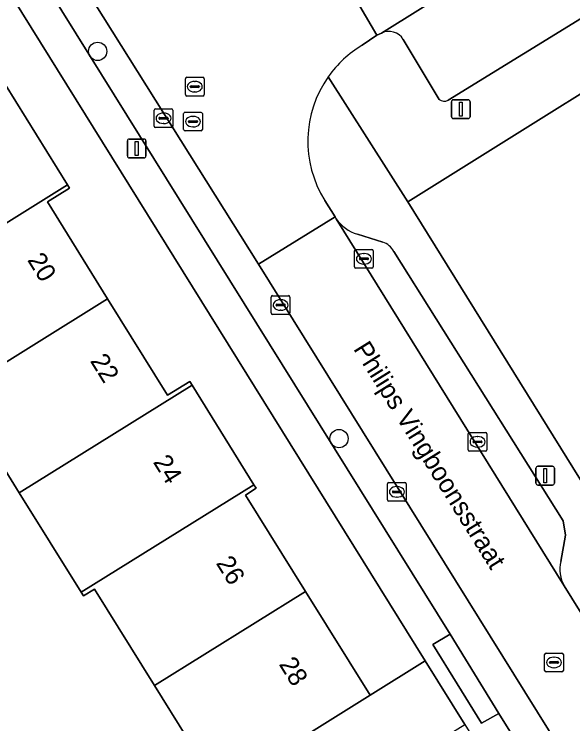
# Model space of a CAD drawing. Extents: x 159352 to 160617, y 385888 to 387323.
# Drawn here: x 159749.73 to 159779.61, y 385991.03 to 386028.96 of the extents above; entities that cross this region are included whole.
import ezdxf

# ---------------------------------------------------------------- set-up
doc = ezdxf.new("R2010")
doc.units = 0
for name, color, linetype in [('IMGEO_Boom', 7, 'Continuous'), ('IMGEO_Erf', 7, 'Continuous'), ('IMGEO_Kolk', 7, 'Continuous'), ('IMGEO_Lichtmast', 7, 'Continuous'), ('IMGEO_Openbare_ruimte_label', 7, 'Continuous'), ('IMGEO_Pand', 7, 'Continuous'), ('IMGEO_Pand_nummerreeks', 7, 'Continuous'), ('IMGEO_Parkeervlak_open', 7, 'Continuous'), ('IMGEO_Rijbaan_lokaal_open', 7, 'Continuous'), ('IMGEO_Rioolput', 7, 'Continuous'), ('IMGEO_Voetpad_open', 7, 'Continuous')]:
    doc.layers.add(name, color=color, linetype=linetype)

msp = doc.modelspace()

# ---------------------------------------------------------------- linework, layer by layer
at = {"layer": 'IMGEO_Boom'}
for centre in [(159754.195, 386026.974), (159767.101, 386006.278)]:
    msp.add_circle(centre, 0.489, dxfattribs=at)
at = {"layer": 'IMGEO_Erf'}
for points in [[(159749.263, 386025.183), (159752.591, 386019.833), (159752.697, 386019.663), (159751.507, 386018.93), (159754.731, 386013.749), (159757.937, 386008.596), (159759.127, 386009.334), (159759.247, 386009.14), (159762.552, 386003.808), (159762.666, 386003.623), (159762.111, 386003.252), (159765.311, 385998.105), (159768.762, 385992.557), (159771.719, 385994.399), (159746.307, 386035.207)], [(159743.864, 385985.314), (159750.4, 385989.412), (159752.465, 385986.118), (159755.303, 385987.897), (159756.968, 385985.218), (159760.702, 385987.531), (159757.239, 385993.08), (159754.026, 385998.227), (159753.441, 385997.869), (159753.321, 385998.062), (159750.006, 386003.387), (159746.677, 386008.735)]]:
    msp.add_lwpolyline(points, dxfattribs=at)
at = {"layer": 'IMGEO_Kolk'}
for p, q in [((159757.218, 386022.972), (159757.218, 386023.824)), ((159757.293, 386023.898), (159758.145, 386023.898)), ((159758.219, 386023.824), (159758.219, 386022.972)), ((159757.52, 386023.441), (159757.918, 386023.441)), ((159757.706, 386023.678), (159757.731, 386023.678)), ((159757.477, 386023.392), (159757.477, 386023.404)), ((159757.915, 386023.355), (159757.517, 386023.355)), ((159757.729, 386023.118), (159757.704, 386023.118)), ((159757.961, 386023.404), (159757.961, 386023.392)), ((159758.145, 386022.898), (159757.293, 386022.898)), ((159767.933, 386015.462), (159767.933, 386016.314)), ((159768.008, 386016.388), (159768.86, 386016.388)), ((159768.934, 386016.314), (159768.934, 386015.462)), ((159768.192, 386015.882), (159768.192, 386015.894)), ((159768.235, 386015.931), (159768.633, 386015.931)), ((159768.421, 386016.168), (159768.446, 386016.168)), ((159768.676, 386015.894), (159768.676, 386015.882)), ((159768.63, 386015.845), (159768.232, 386015.845)), ((159768.444, 386015.608), (159768.419, 386015.608)), ((159768.86, 386015.388), (159768.008, 386015.388)), ((159763.478, 386012.991), (159763.478, 386013.843)), ((159763.553, 386013.917), (159764.405, 386013.917)), ((159763.966, 386013.697), (159763.991, 386013.697)), ((159764.479, 386013.843), (159764.479, 386012.991)), ((159763.737, 386013.411), (159763.737, 386013.423)), ((159764.175, 386013.374), (159763.777, 386013.374)), ((159763.78, 386013.46), (159764.178, 386013.46)), ((159764.221, 386013.423), (159764.221, 386013.411)), ((159764.405, 386012.917), (159763.553, 386012.917)), ((159763.989, 386013.137), (159763.964, 386013.137)), ((159774.009, 386005.68), (159774.009, 386006.532)), ((159774.084, 386006.606), (159774.936, 386006.606)), ((159774.497, 386006.386), (159774.522, 386006.386)), ((159775.01, 386006.532), (159775.01, 386005.68)), ((159774.268, 386006.1), (159774.268, 386006.112)), ((159774.706, 386006.063), (159774.308, 386006.063)), ((159774.311, 386006.149), (159774.709, 386006.149)), ((159774.752, 386006.112), (159774.752, 386006.1)), ((159774.52, 386005.826), (159774.495, 386005.826)), ((159774.936, 386005.606), (159774.084, 386005.606)), ((159769.697, 386003.004), (159769.697, 386003.856)), ((159769.772, 386003.93), (159770.624, 386003.93)), ((159770.698, 386003.856), (159770.698, 386003.004)), ((159769.956, 386003.424), (159769.956, 386003.436)), ((159770.394, 386003.387), (159769.996, 386003.387)), ((159769.999, 386003.473), (159770.397, 386003.473)), ((159770.185, 386003.71), (159770.21, 386003.71)), ((159770.44, 386003.436), (159770.44, 386003.424)), ((159770.208, 386003.15), (159770.183, 386003.15)), ((159770.624, 386002.93), (159769.772, 386002.93))]:
    msp.add_line(p, q, dxfattribs=at)
for points in [[(159757.218, 386022.972), (159757.218, 386023.824)], [(159757.293, 386023.898), (159758.145, 386023.898)], [(159758.219, 386023.824), (159758.219, 386022.972)], [(159758.145, 386022.898), (159757.293, 386022.898)], [(159767.933, 386015.462), (159767.933, 386016.314)], [(159768.008, 386016.388), (159768.86, 386016.388)], [(159768.934, 386016.314), (159768.934, 386015.462)], [(159768.86, 386015.388), (159768.008, 386015.388)], [(159763.478, 386012.991), (159763.478, 386013.843)], [(159763.553, 386013.917), (159764.405, 386013.917)], [(159764.479, 386013.843), (159764.479, 386012.991)], [(159764.405, 386012.917), (159763.553, 386012.917)], [(159774.009, 386005.68), (159774.009, 386006.532)], [(159774.084, 386006.606), (159774.936, 386006.606)], [(159775.01, 386006.532), (159775.01, 386005.68)], [(159774.936, 386005.606), (159774.084, 386005.606)], [(159769.697, 386003.004), (159769.697, 386003.856)], [(159769.772, 386003.93), (159770.624, 386003.93)], [(159770.698, 386003.856), (159770.698, 386003.004)], [(159770.624, 386002.93), (159769.772, 386002.93)]]:
    msp.add_lwpolyline(points, dxfattribs=at)
for centre, radius, start, end in [((159757.295, 386023.822), 0.0765, 91.552, 178.448), ((159757.295, 386023.822), 0.0765, 91.552, 178.448), ((159758.143, 386023.822), 0.0765, 1.552, 88.448), ((159758.143, 386023.822), 0.0765, 1.552, 88.448), ((159757.517, 386023.401), 0.0403, 85.8775, 175.7526), ((159757.922, 386023.403), 0.0386, 1.7309, 96.639), ((159757.514, 386023.391), 0.0366, 178.938, 274.7102), ((159757.918, 386023.398), 0.043, 264.8664, 352.4533), ((159757.295, 386022.974), 0.0765, 181.552, 268.448), ((159757.295, 386022.974), 0.0765, 181.552, 268.448), ((159758.143, 386022.974), 0.0765, 271.552, 358.448), ((159758.143, 386022.974), 0.0765, 271.552, 358.448), ((159768.01, 386016.312), 0.0765, 91.552, 178.448), ((159768.01, 386016.312), 0.0765, 91.552, 178.448), ((159768.858, 386016.312), 0.0765, 1.552, 88.448), ((159768.858, 386016.312), 0.0765, 1.552, 88.448), ((159768.232, 386015.891), 0.0403, 85.8775, 175.7526), ((159768.229, 386015.881), 0.0366, 178.938, 274.7102), ((159768.633, 386015.888), 0.043, 264.8664, 352.4533), ((159768.637, 386015.893), 0.0386, 1.7309, 96.639), ((159768.01, 386015.464), 0.0765, 181.552, 268.448), ((159768.01, 386015.464), 0.0765, 181.552, 268.448), ((159768.858, 386015.464), 0.0765, 271.552, 358.448), ((159768.858, 386015.464), 0.0765, 271.552, 358.448), ((159763.555, 386013.841), 0.0765, 91.552, 178.448), ((159763.555, 386013.841), 0.0765, 91.552, 178.448), ((159764.403, 386013.841), 0.0765, 1.552, 88.448), ((159764.403, 386013.841), 0.0765, 1.552, 88.448), ((159763.777, 386013.42), 0.0403, 85.8775, 175.7526), ((159763.774, 386013.41), 0.0366, 178.938, 274.7102), ((159764.178, 386013.417), 0.043, 264.8664, 352.4533), ((159764.182, 386013.422), 0.0386, 1.7309, 96.639), ((159763.555, 386012.993), 0.0765, 181.552, 268.448), ((159763.555, 386012.993), 0.0765, 181.552, 268.448), ((159764.403, 386012.993), 0.0765, 271.552, 358.448), ((159764.403, 386012.993), 0.0765, 271.552, 358.448), ((159774.086, 386006.53), 0.0765, 91.552, 178.448), ((159774.086, 386006.53), 0.0765, 91.552, 178.448), ((159774.934, 386006.53), 0.0765, 1.552, 88.448), ((159774.934, 386006.53), 0.0765, 1.552, 88.448), ((159774.308, 386006.109), 0.0403, 85.8775, 175.7526), ((159774.305, 386006.099), 0.0366, 178.938, 274.7102), ((159774.709, 386006.106), 0.043, 264.8664, 352.4533), ((159774.713, 386006.111), 0.0386, 1.7309, 96.639), ((159774.086, 386005.682), 0.0765, 181.552, 268.448), ((159774.086, 386005.682), 0.0765, 181.552, 268.448), ((159774.934, 386005.682), 0.0765, 271.552, 358.448), ((159774.934, 386005.682), 0.0765, 271.552, 358.448), ((159769.774, 386003.854), 0.0765, 91.552, 178.448), ((159769.774, 386003.854), 0.0765, 91.552, 178.448), ((159770.622, 386003.854), 0.0765, 1.552, 88.448), ((159770.622, 386003.854), 0.0765, 1.552, 88.448), ((159769.996, 386003.433), 0.0403, 85.8775, 175.7526), ((159769.993, 386003.423), 0.0366, 178.938, 274.7102), ((159770.397, 386003.43), 0.043, 264.8664, 352.4533), ((159770.401, 386003.435), 0.0386, 1.7309, 96.639), ((159769.774, 386003.006), 0.0765, 181.552, 268.448), ((159769.774, 386003.006), 0.0765, 181.552, 268.448), ((159770.622, 386003.006), 0.0765, 271.552, 358.448), ((159770.622, 386003.006), 0.0765, 271.552, 358.448)]:
    msp.add_arc(centre, radius, start, end, dxfattribs=at)
for centre, major_axis, ratio, start_param, end_param in [((159757.705, 386023.398), (-0.387, 0.002), 0.722429, 4.712389, 7.853982), ((159757.73, 386023.398), (-0.39, 0.002), 0.717154, 1.570796, 4.712389), ((159768.42, 386015.888), (-0.387, 0.002), 0.722429, 4.712389, 7.853982), ((159768.445, 386015.888), (-0.39, 0.002), 0.717154, 1.570796, 4.712389), ((159763.965, 386013.417), (-0.387, 0.002), 0.722429, 4.712389, 7.853982), ((159763.99, 386013.417), (-0.39, 0.002), 0.717154, 1.570796, 4.712389), ((159774.496, 386006.106), (-0.387, 0.002), 0.722429, 4.712389, 7.853982), ((159774.521, 386006.106), (-0.39, 0.002), 0.717154, 1.570796, 4.712389), ((159770.184, 386003.43), (-0.387, 0.002), 0.722429, 4.712389, 7.853982), ((159770.209, 386003.43), (-0.39, 0.002), 0.717154, 1.570796, 4.712389)]:
    msp.add_ellipse(centre, major_axis=major_axis, ratio=ratio, start_param=start_param, end_param=end_param, dxfattribs=at)
at = {"layer": 'IMGEO_Lichtmast'}
for p, q in [((159773.12, 386023.484), (159773.12, 386024.284)), ((159773.12, 386024.284), (159773.12, 386023.484)), ((159773.22, 386024.384), (159774.01, 386024.384)), ((159774.01, 386024.384), (159773.22, 386024.384)), ((159774.11, 386024.284), (159774.11, 386023.484)), ((159774.11, 386023.484), (159774.11, 386024.284)), ((159774.01, 386023.384), (159773.22, 386023.384)), ((159773.22, 386023.384), (159774.01, 386023.384)), ((159755.787, 386021.385), (159755.787, 386022.185)), ((159755.787, 386022.185), (159755.787, 386021.385)), ((159755.887, 386022.285), (159756.677, 386022.285)), ((159756.677, 386022.285), (159755.887, 386022.285)), ((159756.777, 386022.185), (159756.777, 386021.385)), ((159756.777, 386021.385), (159756.777, 386022.185)), ((159756.677, 386021.285), (159755.887, 386021.285)), ((159755.887, 386021.285), (159756.677, 386021.285)), ((159777.631, 386003.896), (159777.631, 386004.696)), ((159777.631, 386004.696), (159777.631, 386003.896)), ((159777.731, 386004.796), (159778.521, 386004.796)), ((159778.521, 386004.796), (159777.731, 386004.796)), ((159778.621, 386004.696), (159778.621, 386003.896)), ((159778.621, 386003.896), (159778.621, 386004.696)), ((159778.521, 386003.796), (159777.731, 386003.796)), ((159777.731, 386003.796), (159778.521, 386003.796))]:
    msp.add_line(p, q, dxfattribs=at)
for points in [[(159773.54, 386024.259), (159773.69, 386024.259), (159773.69, 386023.509), (159773.54, 386023.509), (159773.54, 386024.259)], [(159756.207, 386022.16), (159756.357, 386022.16), (159756.357, 386021.41), (159756.207, 386021.41), (159756.207, 386022.16)], [(159778.051, 386004.671), (159778.201, 386004.671), (159778.201, 386003.921), (159778.051, 386003.921), (159778.051, 386004.671)]]:
    msp.add_lwpolyline(points, dxfattribs=at)
for centre, start, end in [((159773.22, 386024.284), 90, 180), ((159773.22, 386024.284), 90, 180), ((159774.01, 386024.284), 0, 90), ((159774.01, 386024.284), 360, 90), ((159773.22, 386023.484), 180, 270), ((159773.22, 386023.484), 180, 270), ((159774.01, 386023.484), 270, 0), ((159774.01, 386023.484), 270, 0), ((159755.887, 386022.185), 90, 180), ((159755.887, 386022.185), 90, 180), ((159756.677, 386022.185), 0, 90), ((159756.677, 386022.185), 360, 90), ((159755.887, 386021.385), 180, 270), ((159755.887, 386021.385), 180, 270), ((159756.677, 386021.385), 270, 0), ((159756.677, 386021.385), 270, 0), ((159777.731, 386004.696), 90, 180), ((159777.731, 386004.696), 90, 180), ((159778.521, 386004.696), 0, 90), ((159778.521, 386004.696), 360, 90), ((159777.731, 386003.896), 180, 270), ((159777.731, 386003.896), 180, 270), ((159778.521, 386003.896), 270, 0), ((159778.521, 386003.896), 270, 0)]:
    msp.add_arc(centre, 0.1, start, end, dxfattribs=at)
at = {"layer": 'IMGEO_Pand'}
for points in [[(159770.784, 386018.94), (159781.076, 386002.383), (159800.515, 386014.52), (159796.689, 386020.663), (159794.008, 386018.98), (159787.689, 386029.088), (159788.029, 386029.306), (159787.845, 386029.593)], [(159752.591, 386019.833), (159749.263, 386025.183), (159740.019, 386019.428), (159743.349, 386014.08)], [(159754.731, 386013.749), (159751.507, 386018.93), (159752.697, 386019.663), (159752.591, 386019.833), (159743.349, 386014.08), (159746.677, 386008.735)], [(159746.677, 386008.735), (159750.006, 386003.387), (159759.247, 386009.14), (159759.127, 386009.334), (159757.937, 386008.596), (159754.731, 386013.749)], [(159762.552, 386003.808), (159759.247, 386009.14), (159750.006, 386003.387), (159753.321, 385998.062)], [(159765.311, 385998.105), (159762.111, 386003.252), (159762.666, 386003.623), (159762.552, 386003.808), (159753.321, 385998.062), (159753.441, 385997.869), (159754.026, 385998.227), (159757.239, 385993.08)], [(159757.239, 385993.08), (159760.702, 385987.531), (159768.762, 385992.557), (159765.311, 385998.105)]]:
    msp.add_lwpolyline(points, close=True, dxfattribs=at)
at = {"layer": 'IMGEO_Parkeervlak_open'}
for points in [[(159790.897, 386041.373), (159769.372, 386027.952)], [(159772.944, 386024.359), (159792.613, 386036.48)], [(159788.248, 385974.74), (159762.791, 386015.603), (159752.658, 386031.759), (159750.194, 386035.775)], [(159750.25, 386032.416), (159773.04, 385995.833), (159775.658, 385991.589), (159779.531, 385985.355), (159785.45, 385976.166)], [(159770.54, 386027.605), (159772.454, 386024.404)], [(159766.946, 386018.026), (159779.143, 385998.41)], [(159769.45, 386016.78), (159768.089, 386017.201)], [(159778.962, 385999.708), (159779.207, 386001.116), (159779.085, 386001.888), (159770.035, 386016.276)]]:
    msp.add_lwpolyline(points, dxfattribs=at)
for centre, radius, start, end in [((159769.765, 386027.135), 0.907, 31.2274, 115.6803), ((159772.735, 386024.779), 0.469, 233.0934, 296.4123), ((159768.705, 386019.259), 2.148, 215.0245, 253.3332), ((159769.153, 386015.844), 0.982, 26.1052, 72.4024), ((159780.725, 385999.292), 1.811, 166.7298, 209.1471)]:
    msp.add_arc(centre, radius, start, end, dxfattribs=at)
at = {"layer": 'IMGEO_Rijbaan_lokaal_open'}
for points in [[(159802.59, 386048.648), (159808.598, 386052.376), (159808.818, 386052.536), (159805.965, 386057.175), (159803.833, 386055.808), (159796.924, 386051.501), (159794.635, 386050.078), (159787.755, 386045.761), (159785.455, 386044.311), (159778.687, 386040.071), (159776.353, 386038.645), (159769.407, 386034.309), (159766.65, 386032.618), (159766.391, 386032.505), (159769.13, 386027.84), (159769.372, 386027.952), (159790.897, 386041.373), (159791.097, 386041.553), (159796.184, 386044.657), (159798.338, 386045.971)], [(159762.791, 386015.603), (159788.248, 385974.74), (159788.6, 385974.171), (159792.653, 385976.684), (159779.143, 385998.41), (159766.946, 386018.026), (159766.892, 386018.124)], [(159767.632, 385987.153), (159770.888, 385989.171), (159773.833, 385991.005), (159771.719, 385994.399), (159768.762, 385992.557), (159760.702, 385987.531), (159756.968, 385985.218), (159754.135, 385983.452), (159747.578, 385979.361), (159746.3, 385978.566), (159739.263, 385974.184), (159725.011, 385965.31), (159722.539, 385963.769), (159724.622, 385960.426), (159753.911, 385978.646), (159755.113, 385979.394)]]:
    msp.add_lwpolyline(points, close=True, dxfattribs=at)
for points in [[(159757.402, 386033.5), (159756.838, 386034.337), (159752.658, 386031.759), (159762.791, 386015.603), (159766.892, 386018.124), (159766.34, 386019.01)], [(159769.13, 386027.84), (159766.391, 386032.505)], [(159768.344, 386027.301), (159769.13, 386027.84)]]:
    msp.add_lwpolyline(points, dxfattribs=at)
for centre, radius, start, end in [((159771.409, 386022.176), 5.972, 120.8816, 144.7548), ((159771.414, 386022.171), 5.978, 144.7469, 211.9265)]:
    msp.add_arc(centre, radius, start, end, dxfattribs=at)
at = {"layer": 'IMGEO_Rioolput'}
for p, q in [((159758.891, 386024.661), (159758.891, 386025.513)), ((159758.966, 386025.587), (159759.818, 386025.587)), ((159759.379, 386025.367), (159759.404, 386025.367)), ((159759.892, 386025.513), (159759.892, 386024.661)), ((159759.15, 386025.081), (159759.15, 386025.093)), ((159759.588, 386025.044), (159759.19, 386025.044)), ((159759.193, 386025.13), (159759.591, 386025.13)), ((159759.634, 386025.093), (159759.634, 386025.081)), ((159759.818, 386024.587), (159758.966, 386024.587)), ((159759.402, 386024.807), (159759.377, 386024.807)), ((159758.796, 386022.794), (159758.796, 386023.646)), ((159758.871, 386023.72), (159759.723, 386023.72)), ((159759.284, 386023.5), (159759.309, 386023.5)), ((159759.797, 386023.646), (159759.797, 386022.794)), ((159759.055, 386023.214), (159759.055, 386023.226)), ((159759.493, 386023.177), (159759.095, 386023.177)), ((159759.098, 386023.263), (159759.496, 386023.263)), ((159759.539, 386023.226), (159759.539, 386023.214)), ((159759.723, 386022.72), (159758.871, 386022.72)), ((159759.307, 386022.94), (159759.282, 386022.94)), ((159778.1, 385993.888), (159778.1, 385994.74)), ((159778.175, 385994.814), (159779.027, 385994.814)), ((159779.101, 385994.74), (159779.101, 385993.888)), ((159778.359, 385994.308), (159778.359, 385994.32)), ((159778.797, 385994.271), (159778.399, 385994.271)), ((159778.402, 385994.357), (159778.8, 385994.357)), ((159778.588, 385994.594), (159778.613, 385994.594)), ((159778.843, 385994.32), (159778.843, 385994.308)), ((159778.611, 385994.034), (159778.586, 385994.034)), ((159779.027, 385993.814), (159778.175, 385993.814))]:
    msp.add_line(p, q, dxfattribs=at)
for points in [[(159758.891, 386024.661), (159758.891, 386025.513)], [(159758.966, 386025.587), (159759.818, 386025.587)], [(159759.892, 386025.513), (159759.892, 386024.661)], [(159759.818, 386024.587), (159758.966, 386024.587)], [(159758.796, 386022.794), (159758.796, 386023.646)], [(159758.871, 386023.72), (159759.723, 386023.72)], [(159759.797, 386023.646), (159759.797, 386022.794)], [(159759.723, 386022.72), (159758.871, 386022.72)], [(159778.1, 385993.888), (159778.1, 385994.74)], [(159778.175, 385994.814), (159779.027, 385994.814)], [(159779.101, 385994.74), (159779.101, 385993.888)], [(159779.027, 385993.814), (159778.175, 385993.814)]]:
    msp.add_lwpolyline(points, dxfattribs=at)
for centre, radius, start, end in [((159758.968, 386025.511), 0.0765, 91.552, 178.448), ((159758.968, 386025.511), 0.0765, 91.552, 178.448), ((159759.816, 386025.511), 0.0765, 1.552, 88.448), ((159759.816, 386025.511), 0.0765, 1.552, 88.448), ((159759.19, 386025.09), 0.0403, 85.8775, 175.7526), ((159759.187, 386025.08), 0.0366, 178.938, 274.7102), ((159759.591, 386025.087), 0.043, 264.8664, 352.4533), ((159759.595, 386025.092), 0.0386, 1.7309, 96.639), ((159758.968, 386024.663), 0.0765, 181.552, 268.448), ((159758.968, 386024.663), 0.0765, 181.552, 268.448), ((159759.816, 386024.663), 0.0765, 271.552, 358.448), ((159759.816, 386024.663), 0.0765, 271.552, 358.448), ((159758.873, 386023.644), 0.0765, 91.552, 178.448), ((159758.873, 386023.644), 0.0765, 91.552, 178.448), ((159759.721, 386023.644), 0.0765, 1.552, 88.448), ((159759.721, 386023.644), 0.0765, 1.552, 88.448), ((159759.095, 386023.223), 0.0403, 85.8775, 175.7526), ((159759.092, 386023.213), 0.0366, 178.938, 274.7102), ((159759.496, 386023.22), 0.043, 264.8664, 352.4533), ((159759.5, 386023.225), 0.0386, 1.7309, 96.639), ((159758.873, 386022.796), 0.0765, 181.552, 268.448), ((159758.873, 386022.796), 0.0765, 181.552, 268.448), ((159759.721, 386022.796), 0.0765, 271.552, 358.448), ((159759.721, 386022.796), 0.0765, 271.552, 358.448), ((159778.177, 385994.738), 0.0765, 91.552, 178.448), ((159778.177, 385994.738), 0.0765, 91.552, 178.448), ((159779.025, 385994.738), 0.0765, 1.552, 88.448), ((159779.025, 385994.738), 0.0765, 1.552, 88.448), ((159778.399, 385994.317), 0.0403, 85.8775, 175.7526), ((159778.396, 385994.307), 0.0366, 178.938, 274.7102), ((159778.8, 385994.314), 0.043, 264.8664, 352.4533), ((159778.804, 385994.319), 0.0386, 1.7309, 96.639), ((159778.177, 385993.89), 0.0765, 181.552, 268.448), ((159778.177, 385993.89), 0.0765, 181.552, 268.448), ((159779.025, 385993.89), 0.0765, 271.552, 358.448), ((159779.025, 385993.89), 0.0765, 271.552, 358.448)]:
    msp.add_arc(centre, radius, start, end, dxfattribs=at)
for centre, major_axis, ratio, start_param, end_param in [((159759.378, 386025.087), (-0.387, 0.002), 0.722429, 4.712389, 7.853982), ((159759.403, 386025.087), (-0.39, 0.002), 0.717154, 1.570796, 4.712389), ((159759.283, 386023.22), (-0.387, 0.002), 0.722429, 4.712389, 7.853982), ((159759.308, 386023.22), (-0.39, 0.002), 0.717154, 1.570796, 4.712389), ((159778.587, 385994.314), (-0.387, 0.002), 0.722429, 4.712389, 7.853982), ((159778.612, 385994.314), (-0.39, 0.002), 0.717154, 1.570796, 4.712389)]:
    msp.add_ellipse(centre, major_axis=major_axis, ratio=ratio, start_param=start_param, end_param=end_param, dxfattribs=at)
at = {"layer": 'IMGEO_Voetpad_open'}
for points in [[(159727.232, 386069.448), (159724.652, 386067.823), (159726.053, 386067.427), (159739.998, 386045.377), (159742.641, 386041.129), (159743.822, 386039.222), (159746.307, 386035.207), (159771.719, 385994.399), (159773.833, 385991.005), (159785.861, 385971.689), (159788.912, 385973.68), (159788.6, 385974.171), (159788.248, 385974.74)], [(159766.532, 386025.622), (159770.784, 386018.94), (159787.845, 386029.593), (159790.097, 386030.999), (159801.54, 386038.089), (159804.855, 386040.143), (159811.969, 386044.648)], [(159792.613, 386036.48), (159772.944, 386024.359)], [(159785.45, 385976.166), (159779.531, 385985.355), (159775.658, 385991.589), (159774.723, 385991.063), (159772.117, 385995.273), (159773.04, 385995.833), (159750.25, 386032.416)], [(159769.372, 386027.952), (159769.13, 386027.84), (159768.344, 386027.301)], [(159772.454, 386024.404), (159770.54, 386027.605)], [(159779.143, 385998.41), (159792.653, 385976.684), (159792.94, 385976.214), (159794.607, 385977.16), (159781.555, 385998.167), (159780.497, 385999.87), (159782.041, 386000.826), (159781.076, 386002.383), (159770.784, 386018.94), (159766.532, 386025.622)], [(159766.34, 386019.01), (159766.892, 386018.124), (159766.946, 386018.026)], [(159768.089, 386017.201), (159769.45, 386016.78)], [(159770.035, 386016.276), (159779.085, 386001.888), (159779.207, 386001.116), (159778.962, 385999.708)]]:
    msp.add_lwpolyline(points, dxfattribs=at)
msp.add_lwpolyline([(159773.04, 385995.833), (159772.117, 385995.273), (159774.723, 385991.063), (159775.658, 385991.589)], close=True, dxfattribs=at)
for centre, radius, start, end in [((159769.765, 386027.135), 0.907, 31.2274, 115.6803), ((159771.409, 386022.176), 5.972, 120.8816, 144.7548), ((159771.414, 386022.171), 5.978, 144.7469, 211.9265), ((159772.735, 386024.779), 0.469, 233.0934, 296.4123), ((159768.705, 386019.259), 2.148, 215.0245, 253.3332), ((159769.153, 386015.844), 0.982, 26.1052, 72.4024), ((159780.725, 385999.292), 1.811, 166.7298, 209.1471)]:
    msp.add_arc(centre, radius, start, end, dxfattribs=at)

# ---------------------------------------------------------------- texts
at = {"layer": 'IMGEO_Openbare_ruimte_label'}
msp.add_text('Philips Vingboonsstraat', height=1, rotation=301.9265, dxfattribs=at).set_placement((159767.846, 386011.074))
at = {"layer": 'IMGEO_Pand_nummerreeks'}
for s, p in [('20', (159750.409, 386015.824)), ('22', (159753.767, 386010.431)), ('24', (159757.134, 386005.025)), ('26', (159760.498, 385999.623)), ('28', (159763.863, 385994.22))]:
    msp.add_text(s, height=1, rotation=301.9115, dxfattribs=at).set_placement(p)

doc.saveas('drawing.dxf')
